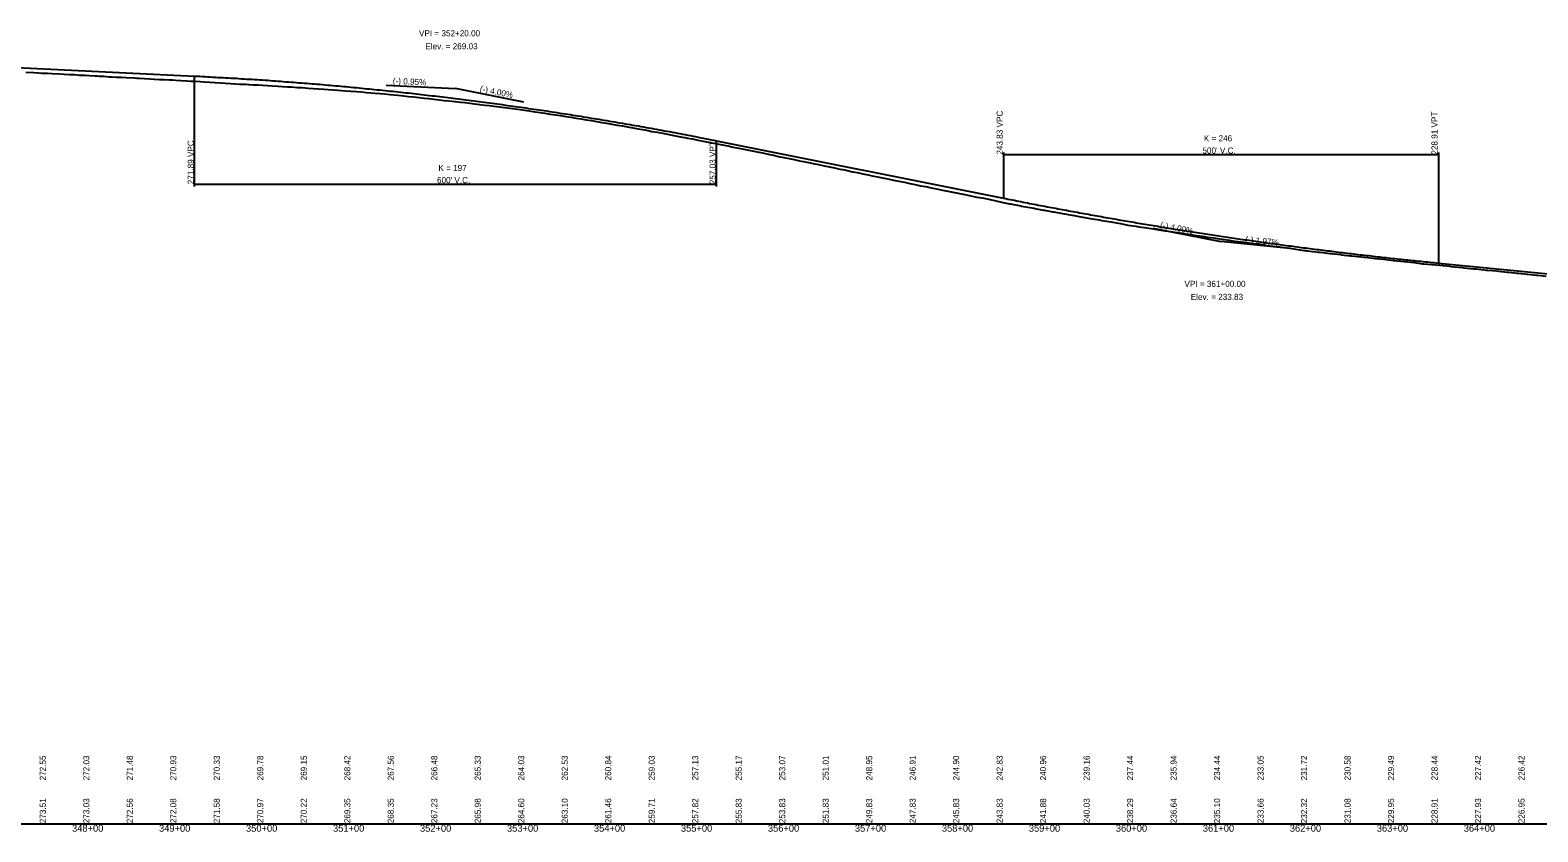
# Model space of a CAD drawing. Extents: x 1876258 to 1932803, y 754739 to 837911.
# Drawn here: x 1913094 to 1914827, y 827954 to 828875 of the extents above; entities that cross this region are included whole.
import ezdxf

# ---------------------------------------------------------------- set-up
doc = ezdxf.new("R2010")
doc.units = 0
for name, color, linetype in [('RD_DDB_GradeTX', 7, 'Continuous'), ('RD_DDB_Profile_EX', 7, 'Continuous'), ('RD_DDB_Profile_Lbl', 7, 'Continuous'), ('RD_DDB_Profile_PR', 7, 'Continuous'), ('RD_DDB_StaTX', 7, 'Continuous'), ('RD_DDB_StripGrade', 7, 'Continuous'), ('RD_DDB_VCLbl', 7, 'Continuous'), ('RD_GPK_Profile_Cell', 7, 'Continuous')]:
    doc.layers.add(name, color=color, linetype=linetype)

msp = doc.modelspace()

# ---------------------------------------------------------------- linework, layer by layer
at = {"layer": 'RD_DDB_GradeTX'}
for p, q in [((1913503.2, 828811.8), (1913583.1, 828808)), ((1913661.5, 828792.3), (1913583.1, 828808)), ((1914384.6, 828647.6), (1914463.1, 828632)), ((1914542.7, 828624.1), (1914463.1, 828632))]:
    msp.add_line(p, q, dxfattribs=at)
at = {"layer": 'RD_DDB_Profile_EX'}
for points in [[(1913088.9, 828826.8), (1913098.1, 828826.3), (1913103.6, 828826), (1913107.4, 828825.8), (1913113.9, 828825.5), (1913119.2, 828825.2), (1913127.9, 828824.8), (1913133.2, 828824.5), (1913138.9, 828824.2), (1913144.8, 828824), (1913150.8, 828823.5), (1913156.8, 828823.2), (1913162.4, 828823), (1913168.8, 828822.6), (1913171.1, 828822.4), (1913173.3, 828822.3), (1913178.8, 828822), (1913184.7, 828821.6), (1913187.4, 828821.5), (1913193.2, 828821.2), (1913198.5, 828820.9), (1913204.3, 828820.6), (1913213.5, 828820.2), (1913216.5, 828820), (1913219.4, 828819.8), (1913225.3, 828819.4), (1913231.6, 828819.1), (1913236.8, 828818.8), (1913242.8, 828818.4), (1913248.2, 828818.2), (1913254.4, 828817.9), (1913258.1, 828817.8), (1913261.4, 828817.5), (1913267.5, 828817.2), (1913274, 828816.9), (1913278.8, 828816.6), (1913284.3, 828816.3), (1913289.6, 828816), (1913294.1, 828815.7), (1913300.6, 828815.2), (1913306.7, 828814.9), (1913313, 828814.5), (1913318.3, 828814.1), (1913324.3, 828813.7), (1913329.7, 828813.4), (1913335.2, 828813.1), (1913339.1, 828812.9), (1913341.6, 828812.8), (1913344.9, 828812.6), (1913346.2, 828812.7), (1913350.5, 828812.4), (1913356, 828812.1), (1913361.3, 828811.8), (1913367.2, 828811.5), (1913372.6, 828811.2), (1913379, 828810.8), (1913383.9, 828810.5), (1913389.8, 828810.1), (1913394.4, 828809.8), (1913401.1, 828809.3), (1913406.6, 828809), (1913413.8, 828808.5), (1913419.5, 828808.1), (1913425.4, 828807.8), (1913431.9, 828807.3), (1913436.8, 828806.9), (1913442.5, 828806.5), (1913447.8, 828806.1), (1913456.4, 828805.4), (1913462.7, 828804.9), (1913469.5, 828804.4), (1913474.8, 828804), (1913480.8, 828803.5), (1913485.7, 828803.1), (1913490.2, 828802.7), (1913496.3, 828802.1), (1913501.6, 828801.7), (1913508.1, 828801), (1913512.1, 828800.7), (1913516.9, 828800.3)], [(1913516.9, 828800.3), (1913523.7, 828799.6), (1913528.9, 828798.9), (1913535, 828798.3), (1913541.3, 828797.6), (1913546.9, 828796.9), (1913552.5, 828796.4), (1913558.1, 828795.8), (1913564.4, 828795.1), (1913570.1, 828794.4), (1913575.9, 828793.8), (1913582.6, 828793), (1913588.8, 828792.4), (1913593.8, 828791.8), (1913599.6, 828791), (1913605, 828790.4), (1913611.1, 828789.7), (1913616.8, 828789), (1913622.2, 828788.3), (1913627.6, 828787.7), (1913633.6, 828787), (1913639.4, 828786.2), (1913645.6, 828785.4), (1913651.6, 828784.5), (1913657.5, 828783.7), (1913662.9, 828783), (1913670, 828781.9), (1913674.8, 828781.2), (1913680.2, 828780.4), (1913685.6, 828779.6), (1913691.5, 828778.7), (1913697.9, 828777.8), (1913703.8, 828776.9), (1913709.9, 828776), (1913715.5, 828775.1), (1913721.5, 828774.1), (1913727.4, 828773.1), (1913733.4, 828772.1), (1913739.1, 828771.2), (1913745.5, 828770.1), (1913751.4, 828769.1), (1913756.8, 828768.1), (1913762.7, 828767.1), (1913768.8, 828766), (1913774.9, 828765.1), (1913782.7, 828763.7), (1913787.1, 828762.8), (1913792.9, 828761.8), (1913798.1, 828760.8), (1913804.7, 828759.6), (1913808.9, 828758.7), (1913814.7, 828757.7), (1913820.9, 828756.6), (1913826.6, 828755.4), (1913832.1, 828754.4), (1913837.9, 828753.3), (1913843.8, 828752.1), (1913846.6, 828751.6), (1913849.8, 828751), (1913855.5, 828750), (1913861.6, 828748.8), (1913867.8, 828747.5), (1913873.7, 828746.4), (1913879.9, 828745.2), (1913885.8, 828744), (1913892, 828742.8), (1913897.9, 828741.6), (1913901.8, 828740.7), (1913907, 828739.8), (1913918.5, 828737.6), (1913929.7, 828735.1), (1913936.1, 828733.9), (1913942.4, 828732.5), (1913948.6, 828731.2), (1913954.3, 828730), (1913960.4, 828728.7), (1913966.5, 828727.5), (1913972.3, 828726.3), (1913978.6, 828725), (1913983, 828724), (1913989, 828722.8), (1913994.3, 828721.8), (1914000.4, 828720.5), (1914006.9, 828719.2), (1914012.9, 828717.9), (1914018.9, 828716.7), (1914025, 828715.3), (1914027.8, 828714.8), (1914033.6, 828713.6), (1914039.6, 828712.4), (1914042.4, 828711.9), (1914044.9, 828711.4), (1914051.4, 828710), (1914057.3, 828708.8), (1914061.9, 828707.8), (1914068.1, 828706.6), (1914074.1, 828705.4), (1914080.1, 828704.1), (1914086.5, 828702.8), (1914092.7, 828701.6), (1914099.2, 828700.2)], [(1914099.2, 828700.2), (1914105.4, 828698.9), (1914111.4, 828697.7), (1914117.6, 828696.3), (1914123.8, 828695.2), (1914130, 828694), (1914136.2, 828692.7), (1914143.1, 828691.3), (1914149.2, 828690), (1914155, 828688.9), (1914160.9, 828687.8), (1914162.6, 828687.4), (1914168.6, 828686.1), (1914182.3, 828683.3), (1914188.5, 828682.2), (1914194.2, 828681.1), (1914202.7, 828679.4), (1914210.7, 828677.4), (1914210.8, 828677.4), (1914220.1, 828675.6), (1914220.5, 828675.5), (1914221, 828675.4), (1914233.1, 828673), (1914233.9, 828672.9), (1914248.5, 828670.3), (1914249.2, 828670.2), (1914259.2, 828668.3), (1914260.2, 828668.1), (1914269.6, 828666.4), (1914270.9, 828666.2), (1914280.8, 828664.3), (1914283.2, 828663.9), (1914291.5, 828662.4), (1914294.2, 828661.9), (1914301.9, 828660.6), (1914304.1, 828660.2), (1914312.7, 828658.7), (1914315.5, 828658.2), (1914323.5, 828656.9), (1914326.2, 828656.4), (1914334.1, 828655.1), (1914336.5, 828654.7), (1914345.1, 828653.2), (1914347.4, 828652.8), (1914356.1, 828651.1), (1914359.1, 828650.6), (1914365.7, 828649.6), (1914368.8, 828649.1), (1914375.3, 828648.1), (1914383, 828647), (1914385, 828646.7), (1914394, 828645.3), (1914396.4, 828644.9), (1914404.7, 828643.7), (1914407.5, 828643.3), (1914415.8, 828642.1), (1914418.9, 828641.6), (1914425.9, 828640.5), (1914427.9, 828640.2), (1914434.9, 828639.2), (1914437.9, 828638.7), (1914444, 828637.8), (1914447.3, 828637.3), (1914454.8, 828636.2), (1914458.8, 828635.6), (1914464.9, 828634.8), (1914467.6, 828634.3), (1914472.9, 828633.6), (1914476.4, 828633.1), (1914482.9, 828632.2), (1914486.3, 828631.7), (1914492.5, 828630.9), (1914495.3, 828630.5), (1914500.7, 828629.8), (1914506.3, 828629), (1914509.3, 828628.6), (1914516.2, 828627.6), (1914519.3, 828627.2), (1914526.8, 828626.3), (1914530.3, 828625.9), (1914535.4, 828625.3), (1914539.1, 828624.8), (1914544.4, 828624.1), (1914546.7, 828623.7), (1914558.8, 828622), (1914561.1, 828621.7), (1914562.1, 828621.5), (1914575.2, 828620), (1914577.4, 828619.8), (1914588.2, 828618.5), (1914590.1, 828618.3), (1914600.7, 828617.1), (1914601.4, 828617), (1914611.9, 828615.8), (1914612.7, 828615.8), (1914613.4, 828615.7), (1914627.9, 828614.2), (1914631.9, 828613.7), (1914632, 828613.7), (1914637.5, 828613), (1914640.8, 828612.6)], [(1914640.8, 828612.6), (1914640.9, 828612.6), (1914649.8, 828611.7), (1914649.9, 828611.7), (1914661.3, 828610.5), (1914661.5, 828610.5), (1914669.7, 828609.5), (1914670, 828609.5), (1914685.1, 828608), (1914686.5, 828607.9), (1914687.7, 828607.8), (1914694.9, 828606.6), (1914696.4, 828606.5), (1914714.5, 828604.9), (1914714.6, 828604.8), (1914714.8, 828604.8), (1914726.5, 828603.7), (1914727.1, 828603.6), (1914740.8, 828602.1), (1914742.2, 828602), (1914753.3, 828600.9), (1914754.5, 828600.8), (1914756.3, 828600.6), (1914768, 828599.4), (1914769.7, 828599.2), (1914780.4, 828598.3), (1914782.6, 828598), (1914792.2, 828597), (1914794, 828596.8), (1914803.7, 828595.9), (1914805.2, 828595.7), (1914814.6, 828594.8), (1914815.5, 828594.7), (1914825.8, 828593.5), (1914826.9, 828593.4), (1914836.8, 828592.4)]]:
    msp.add_lwpolyline(points, dxfattribs=at)
at = {"layer": 'RD_DDB_Profile_PR'}
for p, q in [((1912568.1, 828856.3), (1913283.1, 828822.3)), ((1913883.1, 828748), (1914213.1, 828682)), ((1914713.1, 828607.4), (1915390.6, 828540.7))]:
    msp.add_line(p, q, dxfattribs=at)
for points in [[(1913283.1, 828822.3), (1913295.1, 828821.7), (1913307.1, 828821), (1913319.1, 828820.4), (1913331.1, 828819.7), (1913343.1, 828818.9), (1913355.1, 828818.2), (1913367.1, 828817.4), (1913379.1, 828816.5), (1913391.1, 828815.6), (1913403.1, 828814.7), (1913415.1, 828813.8), (1913427.1, 828812.8), (1913439.1, 828811.7), (1913451.1, 828810.7), (1913463.1, 828809.6), (1913475.1, 828808.4), (1913487.1, 828807.2), (1913499.1, 828806), (1913511.1, 828804.8), (1913523.1, 828803.5), (1913535.1, 828802.2), (1913547.1, 828800.8), (1913559.1, 828799.4), (1913571.1, 828798), (1913583.1, 828796.5), (1913595.1, 828795), (1913607.1, 828793.5), (1913619.1, 828791.9), (1913631.1, 828790.3), (1913643.1, 828788.6), (1913655.1, 828787), (1913667.1, 828785.2), (1913679.1, 828783.5), (1913691.1, 828781.7), (1913703.1, 828779.8), (1913715.1, 828778), (1913727.1, 828776.1), (1913739.1, 828774.1), (1913751.1, 828772.1), (1913763.1, 828770.1), (1913775.1, 828768.1), (1913787.1, 828766), (1913799.1, 828763.9), (1913811.1, 828761.7), (1913823.1, 828759.5), (1913835.1, 828757.3), (1913847.1, 828755), (1913859.1, 828752.7), (1913871.1, 828750.3), (1913883.1, 828748)], [(1914213.1, 828682), (1914223.1, 828680), (1914233.1, 828678), (1914243.1, 828676), (1914253.1, 828674.1), (1914263.1, 828672.2), (1914273.1, 828670.3), (1914283.1, 828668.5), (1914293.1, 828666.6), (1914303.1, 828664.8), (1914313.1, 828663), (1914323.1, 828661.2), (1914333.1, 828659.4), (1914343.1, 828657.7), (1914353.1, 828655.9), (1914363.1, 828654.2), (1914373.1, 828652.6), (1914383.1, 828650.9), (1914393.1, 828649.2), (1914403.1, 828647.6), (1914413.1, 828646), (1914423.1, 828644.4), (1914433.1, 828642.9), (1914443.1, 828641.3), (1914453.1, 828639.8), (1914463.1, 828638.3), (1914473.1, 828636.8), (1914483.1, 828635.4), (1914493.1, 828633.9), (1914503.1, 828632.5), (1914513.1, 828631.1), (1914523.1, 828629.7), (1914533.1, 828628.4), (1914543.1, 828627), (1914553.1, 828625.7), (1914563.1, 828624.4), (1914573.1, 828623.1), (1914583.1, 828621.9), (1914593.1, 828620.6), (1914603.1, 828619.4), (1914613.1, 828618.2), (1914623.1, 828617), (1914633.1, 828615.9), (1914643.1, 828614.7), (1914653.1, 828613.6), (1914663.1, 828612.5), (1914673.1, 828611.5), (1914683.1, 828610.4), (1914693.1, 828609.4), (1914703.1, 828608.4), (1914713.1, 828607.4)]]:
    msp.add_spline(points, degree=3, dxfattribs=at)
at = {"layer": 'RD_DDB_VCLbl'}
for p, q in [((1913283.1, 828695.5), (1913283.1, 828822.3)), ((1913883.1, 828695.5), (1913883.1, 828748)), ((1914213.1, 828734.5), (1914213.1, 828682)), ((1914213.1, 828732), (1914713.1, 828732)), ((1914713.1, 828734.5), (1914713.1, 828607.4)), ((1913283.1, 828698), (1913883.1, 828698))]:
    msp.add_line(p, q, dxfattribs=at)
at = {"layer": 'RD_GPK_Profile_Cell'}
msp.add_line((1878363.1, 827962.8), (1926563.1, 827962.8), dxfattribs=at)

# ---------------------------------------------------------------- texts
at = {"layer": 'RD_DDB_GradeTX'}
for s, rotation, p in [('(-) 0.95%', 357.2705, (1913510.9, 828813.4)), ('(-) 4.00%', 348.6901, (1913610.6, 828804.5)), ('(-) 4.00%', 348.6901, (1914392.6, 828648.1)), ('(-) 1.97%', 354.383, (1914490.8, 828631.2))]:
    msp.add_text(s, height=7, rotation=rotation, dxfattribs=at).set_placement(p)
at = {"layer": 'RD_DDB_Profile_Lbl'}
for s, p in [('VPI = 352+20.00', (1913541.1, 828868)), ('Elev. = 269.03', (1913548.4, 828853)), ('VPI = 361+00.00', (1914421.1, 828580)), ('Elev. = 233.83', (1914428.4, 828565))]:
    msp.add_text(s, height=7, dxfattribs=at).set_placement(p)
at = {"layer": 'RD_DDB_StaTX'}
for s, p in [('348+00', (1913142.2, 827953.8)), ('349+00', (1913242.2, 827953.8)), ('350+00', (1913342.2, 827953.8)), ('351+00', (1913442.2, 827953.8)), ('352+00', (1913542.2, 827953.8)), ('353+00', (1913642.2, 827953.8)), ('354+00', (1913742.2, 827953.8)), ('355+00', (1913842.2, 827953.8)), ('356+00', (1913942.2, 827953.8)), ('357+00', (1914042.2, 827953.8)), ('358+00', (1914142.2, 827953.8)), ('359+00', (1914242.2, 827953.8)), ('360+00', (1914342.2, 827953.8)), ('361+00', (1914442.2, 827953.8)), ('362+00', (1914542.2, 827953.8)), ('363+00', (1914642.2, 827953.8)), ('364+00', (1914742.2, 827953.8))]:
    msp.add_text(s, height=8, dxfattribs=at).set_placement(p)
at = {"layer": 'RD_DDB_StripGrade'}
for s, p in [('243.83 VPC', (1914212.1, 828732)), ('228.91 VPT', (1914712.1, 828732)), ('271.89 VPC', (1913282.1, 828698)), ('257.03 VPT', (1913882.1, 828698)), ('272.55', (1913112.1, 828012.8)), ('272.03', (1913162.1, 828012.8)), ('271.48', (1913212.1, 828012.8)), ('270.93', (1913262.1, 828012.8)), ('270.33', (1913312.1, 828012.8)), ('269.78', (1913362.1, 828012.8)), ('269.15', (1913412.1, 828012.8)), ('268.42', (1913462.1, 828012.8)), ('267.56', (1913512.1, 828012.8)), ('266.48', (1913562.1, 828012.8)), ('265.33', (1913612.1, 828012.8)), ('264.03', (1913662.1, 828012.8)), ('262.53', (1913712.1, 828012.8)), ('260.84', (1913762.1, 828012.8)), ('259.03', (1913812.1, 828012.8)), ('257.13', (1913862.1, 828012.8)), ('255.17', (1913912.1, 828012.8)), ('253.07', (1913962.1, 828012.8)), ('251.01', (1914012.1, 828012.8)), ('248.95', (1914062.1, 828012.8)), ('246.91', (1914112.1, 828012.8)), ('244.90', (1914162.1, 828012.8)), ('242.83', (1914212.1, 828012.8)), ('240.96', (1914262.1, 828012.8)), ('239.16', (1914312.1, 828012.8)), ('237.44', (1914362.1, 828012.8)), ('235.94', (1914412.1, 828012.8)), ('234.44', (1914462.1, 828012.8)), ('233.05', (1914512.1, 828012.8)), ('231.72', (1914562.1, 828012.8)), ('230.58', (1914612.1, 828012.8)), ('229.49', (1914662.1, 828012.8)), ('228.44', (1914712.1, 828012.8)), ('227.42', (1914762.1, 828012.8)), ('226.42', (1914812.1, 828012.8)), ('273.51', (1913112.1, 827963.6)), ('273.03', (1913162.1, 827963.6)), ('272.56', (1913212.1, 827963.6)), ('272.08', (1913262.1, 827963.6)), ('271.58', (1913312.1, 827963.6)), ('270.97', (1913362.1, 827963.6)), ('270.22', (1913412.1, 827963.6)), ('269.35', (1913462.1, 827963.6)), ('268.35', (1913512.1, 827963.6)), ('267.23', (1913562.1, 827963.6)), ('265.98', (1913612.1, 827963.6)), ('264.60', (1913662.1, 827963.6)), ('263.10', (1913712.1, 827963.6)), ('261.46', (1913762.1, 827963.6)), ('259.71', (1913812.1, 827963.6)), ('257.82', (1913862.1, 827963.6)), ('255.83', (1913912.1, 827963.6)), ('253.83', (1913962.1, 827963.6)), ('251.83', (1914012.1, 827963.6)), ('249.83', (1914062.1, 827963.6)), ('247.83', (1914112.1, 827963.6)), ('245.83', (1914162.1, 827963.6)), ('243.83', (1914212.1, 827963.6)), ('241.88', (1914262.1, 827963.6)), ('240.03', (1914312.1, 827963.6)), ('238.29', (1914362.1, 827963.6)), ('236.64', (1914412.1, 827963.6)), ('235.10', (1914462.1, 827963.6)), ('233.66', (1914512.1, 827963.6)), ('232.32', (1914562.1, 827963.6)), ('231.08', (1914612.1, 827963.6)), ('229.95', (1914662.1, 827963.6)), ('228.91', (1914712.1, 827963.6)), ('227.93', (1914762.1, 827963.6)), ('226.95', (1914812.1, 827963.6))]:
    msp.add_text(s, height=7, rotation=90, dxfattribs=at).set_placement(p)
at = {"layer": 'RD_DDB_VCLbl'}
for s, p in [('K = 246', (1914443.4, 828747.2)), ("500' V.C.", (1914441.8, 828733.2)), ('K = 197', (1913563.4, 828713.2)), ("600' V.C.", (1913561.8, 828699.2))]:
    msp.add_text(s, height=7, dxfattribs=at).set_placement(p)

doc.saveas('drawing.dxf')
